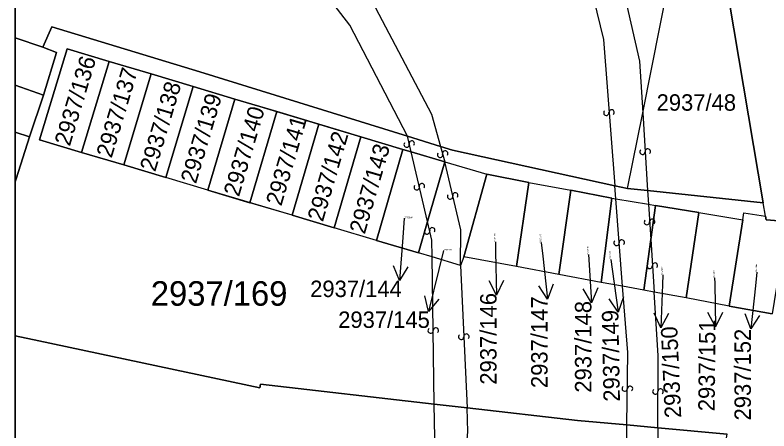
# Model space of a CAD drawing. Extents: x -596024 to -594475, y -1163820 to -1161957.
# Drawn here: x -596024.4 to -595972.1, y -1163190.6 to -1163161.8 of the extents above; entities that cross this region are included whole.
import ezdxf

# ---------------------------------------------------------------- set-up
doc = ezdxf.new("R2010")
doc.units = 0
for name, color, linetype in [('Level 1', 7, 'Continuous'), ('Level 13', 7, 'Continuous'), ('Level 3', 7, 'Continuous'), ('Level 4', 7, 'Continuous'), ('Level 57', 7, 'Continuous'), ('Level 60', 7, 'Continuous'), ('Vrstva 60', 7, 'Continuous'), ('Vrstva 63', 7, 'Continuous')]:
    doc.layers.add(name, color=color, linetype=linetype)

msp = doc.modelspace()

# ---------------------------------------------------------------- linework, layer by layer
at = {"layer": 'Level 1'}
for p, q in [((-596024.42, -1163163.373), (-596022.5, -1163164.02)), ((-596024.42, -1163166.662), (-596022.45, -1163167.35)), ((-596023.41, -1163170.25), (-596024.42, -1163169.907)), ((-596024.42, -1163173.127), (-596024.35, -1163173.15)), ((-596024.35, -1163173.15), (-596024.42, -1163173.362))]:
    msp.add_line(p, q, dxfattribs=at)
for points in [[(-595980.87, -1163168.57), (-595978.45, -1163156.45)], [(-595972.5, -1163174.81), (-595975.56, -1163156.7)], [(-596022.5, -1163164.02), (-596021.88, -1163162.61), (-596011.6, -1163165.73), (-595997.19, -1163170.2)], [(-596022.45, -1163167.35), (-596021.55, -1163164.4), (-596022.5, -1163164.02)], [(-596017.9, -1163165.01), (-596020.8, -1163164.14), (-596022.72, -1163170.46), (-596019.81, -1163171.33)], [(-596017.9, -1163165.01), (-596019.81, -1163171.33)], [(-596014.98, -1163165.88), (-596017.9, -1163165.01)], [(-596016.88, -1163172.19), (-596014.98, -1163165.88)], [(-596012.07, -1163166.75), (-596014.98, -1163165.88)], [(-596013.96, -1163173.06), (-596012.07, -1163166.75)], [(-596009.16, -1163167.62), (-596012.07, -1163166.75)], [(-596022.45, -1163167.35), (-596023.41, -1163170.25)], [(-596009.16, -1163167.62), (-596011.04, -1163173.94)], [(-596006.25, -1163168.49), (-596009.16, -1163167.62)], [(-596008.12, -1163174.81), (-596006.25, -1163168.49)], [(-596003.34, -1163169.36), (-596006.25, -1163168.49)], [(-595981.92, -1163173.82), (-595980.87, -1163168.57)], [(-596003.34, -1163169.36), (-596005.2, -1163175.68)], [(-596000.43, -1163170.23), (-596003.34, -1163169.36)], [(-596023.41, -1163170.25), (-596024.35, -1163173.15)], [(-596002.28, -1163176.54), (-596000.43, -1163170.23)], [(-595997.52, -1163171.11), (-596000.43, -1163170.23)], [(-595997.19, -1163170.2), (-595994.9, -1163170.91)], [(-595982.81, -1163173.63), (-595994.06, -1163171.17), (-595994.9, -1163170.91)], [(-596019.81, -1163171.33), (-596016.88, -1163172.19)], [(-595997.52, -1163171.11), (-595999.35, -1163177.42)], [(-595996.94, -1163171.28), (-595997.52, -1163171.11)], [(-595994.6, -1163171.97), (-595996.94, -1163171.28)], [(-596016.88, -1163172.19), (-596013.96, -1163173.06)], [(-595995.8, -1163176.12), (-595994.6, -1163171.97)], [(-595994.6, -1163171.97), (-595991.69, -1163172.84)], [(-595991.69, -1163172.84), (-595993.27, -1163178.56)], [(-595988.78, -1163173.4), (-595991.69, -1163172.84)], [(-596011.04, -1163173.94), (-596013.96, -1163173.06)], [(-595989.63, -1163179.24), (-595988.78, -1163173.4)], [(-595988.78, -1163173.4), (-595985.86, -1163173.95)], [(-596011.04, -1163173.94), (-596008.12, -1163174.81)], [(-595985.86, -1163173.95), (-595986.69, -1163179.79)], [(-595983.01, -1163174.5), (-595985.86, -1163173.95)], [(-595982.81, -1163173.63), (-595981.92, -1163173.82)], [(-595981.92, -1163173.82), (-595980.53, -1163173.97)], [(-595980.53, -1163173.97), (-595972.5, -1163174.81)], [(-595983.74, -1163180.33), (-595983.01, -1163174.5)], [(-595983.01, -1163174.5), (-595982.73, -1163174.55)], [(-595982.73, -1163174.55), (-595980.47, -1163174.92)], [(-596005.2, -1163175.68), (-596008.12, -1163174.81)], [(-595980.47, -1163174.92), (-595979.99, -1163175)], [(-595979.99, -1163175), (-595980.31, -1163177.35)], [(-595976.97, -1163175.49), (-595979.99, -1163175)], [(-595972.34, -1163175.74), (-595972.5, -1163174.81)], [(-595977.85, -1163181.41), (-595976.97, -1163175.49)], [(-595976.97, -1163175.49), (-595973.93, -1163176)], [(-595973.93, -1163176), (-595973.85, -1163175.51), (-595972.34, -1163175.74)], [(-596005.2, -1163175.68), (-596002.28, -1163176.54)], [(-595996.43, -1163178.29), (-595995.8, -1163176.12)], [(-595973.93, -1163176), (-595974.87, -1163181.97)], [(-595972.34, -1163175.74), (-595972.3, -1163176), (-595970.84, -1163176.11)], [(-595999.35, -1163177.42), (-596002.28, -1163176.54)], [(-595999.35, -1163177.42), (-595996.43, -1163178.29)], [(-595980.31, -1163177.35), (-595980.8, -1163180.87)], [(-595995.48, -1163178.57), (-595996.43, -1163178.29)], [(-595993.51, -1163179.16), (-595995.48, -1163178.57)], [(-595993.27, -1163178.56), (-595993.51, -1163179.16)], [(-595989.63, -1163179.24), (-595993.27, -1163178.56)], [(-595986.69, -1163179.79), (-595989.63, -1163179.24)], [(-595983.74, -1163180.33), (-595986.69, -1163179.79)], [(-595982.26, -1163180.6), (-595983.74, -1163180.33)], [(-595980.8, -1163180.87), (-595982.26, -1163180.6)], [(-595980.08, -1163181), (-595980.8, -1163180.87)], [(-595977.85, -1163181.41), (-595980.08, -1163181)], [(-595974.87, -1163181.97), (-595977.85, -1163181.41)], [(-595974.87, -1163181.97), (-595971.88, -1163182.51)], [(-596024.42, -1163184.047), (-596022.76, -1163184.39), (-596007.44, -1163187.64), (-596007.39, -1163187.4), (-595995.33, -1163188.77)], [(-595995.33, -1163188.77), (-595993.06, -1163189.03)], [(-595981.96, -1163190.21), (-595985.4, -1163189.9), (-595993.06, -1163189.03)], [(-595981.96, -1163190.21), (-595979.83, -1163190.41)], [(-595979.83, -1163190.41), (-595975, -1163190.85)]]:
    msp.add_lwpolyline(points, dxfattribs=at)
at = {"layer": 'Level 13'}
for centre, start, end in [((-595983.394, -1163168.574), 131.6175, 4.2075), ((-595983.026, -1163168.547), 311.832, 183.93), ((-595997.25, -1163170.78), 140.4061, 12.5041), ((-595996.891, -1163170.699), 320.1916, 192.7816), ((-595994.927, -1163171.489), 142.9608, 15.5508), ((-595994.572, -1163171.391), 323.1752, 195.2732), ((-595980.884, -1163171.281), 130.761, 3.351), ((-595980.516, -1163171.26), 310.9755, 183.0735), ((-595996.191, -1163173.659), 320.412, 193.002), ((-595996.55, -1163173.741), 140.6265, 12.7244), ((-595994.23, -1163174.38), 140.4646, 12.5626), ((-595993.871, -1163174.299), 320.2502, 192.8402), ((-595980.574, -1163176.151), 130.9254, 3.5154), ((-595980.206, -1163176.13), 311.1399, 183.2379), ((-595995.471, -1163176.719), 320.3489, 192.9389), ((-595995.83, -1163176.8), 140.5633, 12.6613), ((-595982.684, -1163177.593), 131.8149, 3.9129), ((-595982.316, -1163177.567), 311.6004, 184.1904), ((-595980.384, -1163179.191), 130.7639, 3.3539), ((-595980.016, -1163179.17), 310.9784, 183.0764), ((-595995.584, -1163183.671), 128.2153, 0.3133), ((-595995.216, -1163183.668), 308.0008, 180.5908), ((-595993.464, -1163184.108), 129.7687, 2.3587), ((-595993.096, -1163184.093), 309.9832, 182.0812), ((-595982.114, -1163187.696), 126.6866, 358.7846), ((-595981.746, -1163187.703), 306.4721, 179.0621), ((-595979.994, -1163187.897), 127.0297, 359.1276), ((-595979.626, -1163187.902), 306.8152, 179.4052)]:
    msp.add_arc(centre, 0.184, start, end, dxfattribs=at)
at = {"layer": 'Level 3'}
for points in [[(-596022.62, -1163147.46), (-596010.7, -1163150.2), (-596003.3, -1163156.24), (-595999.4, -1163161.3), (-595995.53, -1163168.66), (-595994.9, -1163170.91)], [(-595997.19, -1163170.2), (-596001.2, -1163162.5), (-596004.77, -1163157.82), (-596011.4, -1163152.2), (-596023.6, -1163149.47)], [(-595985.85, -1163154.18), (-595983.6, -1163163.5), (-595982.81, -1163173.63)], [(-595983.38, -1163154.94), (-595981.1, -1163165), (-595980.87, -1163168.57)], [(-595980.87, -1163168.57), (-595980.53, -1163173.97)], [(-595996.94, -1163171.28), (-595997.19, -1163170.2)], [(-595994.9, -1163170.91), (-595994.6, -1163171.97)], [(-595995.8, -1163176.12), (-595996.94, -1163171.28)], [(-595993.51, -1163179.16), (-595993.5, -1163176.7), (-595994.6, -1163171.97)], [(-595982.73, -1163174.55), (-595982.81, -1163173.63)], [(-595980.53, -1163173.97), (-595980.47, -1163174.92)], [(-595982.26, -1163180.6), (-595982.73, -1163174.55)], [(-595980.47, -1163174.92), (-595980.31, -1163177.35)], [(-595995.48, -1163178.57), (-595995.5, -1163177.4), (-595995.8, -1163176.12)], [(-595980.31, -1163177.35), (-595980.08, -1163181)], [(-595995.33, -1163188.77), (-595995.48, -1163178.57)], [(-595993.51, -1163179.16), (-595993.06, -1163189.03)], [(-595981.96, -1163190.21), (-595981.9, -1163185.2), (-595982.26, -1163180.6)], [(-595979.83, -1163190.41), (-595979.8, -1163185.4), (-595980.08, -1163181)], [(-595995.74, -1163201), (-595995.3, -1163191.1), (-595995.33, -1163188.77)], [(-595993.93, -1163201.27), (-595993, -1163190.7), (-595993.06, -1163189.03)], [(-595982.1, -1163201.3), (-595981.96, -1163190.21)], [(-595979.83, -1163190.41), (-595979.9, -1163201.1)]]:
    msp.add_lwpolyline(points, dxfattribs=at)
at = {"layer": 'Level 57'}
for p, q in [((-595997.41, -1163175.88), (-595997.512, -1163177.219)), ((-595997.512, -1163177.219), (-595997.74, -1163180.21)), ((-595991.09, -1163177.53), (-595991.075, -1163178.221)), ((-595987.91, -1163177.57), (-595987.804, -1163178.522)), ((-595994.68, -1163178.12), (-595995.011, -1163179.44)), ((-595991.075, -1163178.221), (-595991.01, -1163181.22)), ((-595987.804, -1163178.522), (-595987.47, -1163181.503)), ((-595984.64, -1163178.41), (-595984.618, -1163178.756)), ((-595984.618, -1163178.756), (-595984.43, -1163181.75)), ((-595983.09, -1163178.75), (-595982.992, -1163179.42)), ((-595995.011, -1163179.44), (-595995.74, -1163182.35)), ((-595982.992, -1163179.42), (-595982.56, -1163182.389)), ((-595972.94, -1163179.62), (-595973.042, -1163180.577)), ((-595979.47, -1163179.82), (-595979.496, -1163180.478)), ((-595975.88, -1163180.01), (-595975.873, -1163180.421)), ((-595979.496, -1163180.478), (-595979.614, -1163183.476)), ((-595975.873, -1163180.421), (-595975.82, -1163183.421)), ((-595973.042, -1163180.577), (-595973.36, -1163183.56))]:
    msp.add_line(p, q, dxfattribs=at)
for points in [[(-595997.165, -1163179.251), (-595997.74, -1163180.21), (-595998.163, -1163179.175)], [(-595990.532, -1163180.21), (-595991.01, -1163181.22), (-595991.532, -1163180.231)], [(-595987.085, -1163180.454), (-595987.47, -1163181.503), (-595988.079, -1163180.565)], [(-595983.993, -1163180.721), (-595984.43, -1163181.75), (-595984.992, -1163180.783)], [(-595995.012, -1163181.502), (-595995.74, -1163182.35), (-595995.982, -1163181.258)], [(-595982.209, -1163181.327), (-595982.56, -1163182.389), (-595983.199, -1163181.471)], [(-595975.338, -1163182.412), (-595975.82, -1163183.421), (-595976.338, -1163182.429)], [(-595979.075, -1163182.496), (-595979.614, -1163183.476), (-595980.074, -1163182.457)], [(-595972.757, -1163182.619), (-595973.36, -1163183.56), (-595973.751, -1163182.513)]]:
    msp.add_lwpolyline(points, dxfattribs=at)
at = {"layer": 'Level 60'}
for points in [[(-595975.56, -1163156.7), (-595972.5, -1163174.81), (-595980.53, -1163173.97), (-595981.92, -1163173.82), (-595980.87, -1163168.57), (-595978.45, -1163156.45)], [(-595934.8, -1163175.73), (-595935.01, -1163178.73), (-595935.64, -1163178.68), (-595964.77, -1163176.56), (-595967.76, -1163176.33), (-595970.84, -1163176.11), (-595972.3, -1163176), (-595972.34, -1163175.74), (-595972.5, -1163174.81), (-595975.56, -1163156.7), (-595967.15, -1163157.44), (-595937.14, -1163160.09), (-595934.14, -1163160.35), (-595934.28, -1163163.52), (-595934.41, -1163166.54), (-595934.54, -1163169.53), (-595934.67, -1163172.64)], [(-596017.9, -1163165.01), (-596019.81, -1163171.33), (-596022.72, -1163170.46), (-596020.8, -1163164.14)], [(-596017.9, -1163165.01), (-596014.98, -1163165.88), (-596016.88, -1163172.19), (-596019.81, -1163171.33)], [(-596012.07, -1163166.75), (-596013.96, -1163173.06), (-596016.88, -1163172.19), (-596014.98, -1163165.88)], [(-596009.16, -1163167.62), (-596011.04, -1163173.94), (-596013.96, -1163173.06), (-596012.07, -1163166.75)], [(-596006.25, -1163168.49), (-596008.12, -1163174.81), (-596011.04, -1163173.94), (-596009.16, -1163167.62)], [(-596003.34, -1163169.36), (-596005.2, -1163175.68), (-596008.12, -1163174.81), (-596006.25, -1163168.49)], [(-596000.43, -1163170.23), (-596002.28, -1163176.54), (-596005.2, -1163175.68), (-596003.34, -1163169.36)], [(-595997.52, -1163171.11), (-595999.35, -1163177.42), (-596002.28, -1163176.54), (-596000.43, -1163170.23)], [(-595999.35, -1163177.42), (-595997.52, -1163171.11), (-595996.94, -1163171.28), (-595994.6, -1163171.97), (-595995.8, -1163176.12), (-595996.43, -1163178.29)], [(-595991.69, -1163172.84), (-595993.27, -1163178.56), (-595993.51, -1163179.16), (-595995.48, -1163178.57), (-595996.43, -1163178.29), (-595995.8, -1163176.12), (-595994.6, -1163171.97)], [(-595988.78, -1163173.4), (-595989.63, -1163179.24), (-595993.27, -1163178.56), (-595991.69, -1163172.84)], [(-595985.86, -1163173.95), (-595986.69, -1163179.79), (-595989.63, -1163179.24), (-595988.78, -1163173.4)], [(-595983.01, -1163174.5), (-595983.74, -1163180.33), (-595986.69, -1163179.79), (-595985.86, -1163173.95)], [(-595983.74, -1163180.33), (-595983.01, -1163174.5), (-595982.73, -1163174.55), (-595980.47, -1163174.92), (-595979.99, -1163175), (-595980.31, -1163177.35), (-595980.8, -1163180.87), (-595982.26, -1163180.6)], [(-595976.97, -1163175.49), (-595977.85, -1163181.41), (-595980.08, -1163181), (-595980.8, -1163180.87), (-595980.31, -1163177.35), (-595979.99, -1163175)], [(-595973.93, -1163176), (-595974.87, -1163181.97), (-595977.85, -1163181.41), (-595976.97, -1163175.49)], [(-595972.34, -1163175.74), (-595972.3, -1163176), (-595970.84, -1163176.11), (-595971.88, -1163182.51), (-595974.87, -1163181.97), (-595973.93, -1163176), (-595973.85, -1163175.51)]]:
    msp.add_lwpolyline(points, close=True, dxfattribs=at)
at = {"layer": 'Vrstva 60'}
for points in [[(-596024.42, -1163151.144), (-596024.42, -1163163.373), (-596022.5, -1163164.02), (-596021.88, -1163162.61), (-596011.6, -1163165.73), (-595997.19, -1163170.2), (-595994.9, -1163170.91), (-595994.06, -1163171.17), (-595982.81, -1163173.63), (-595981.92, -1163173.82), (-595980.87, -1163168.57), (-595978.45, -1163156.45), (-595983.38, -1163154.94), (-595985.85, -1163154.18), (-595992.05, -1163153.51), (-596004.08, -1163149.95), (-596011.4, -1163147.5), (-596012.73, -1163146.91), (-596019.54, -1163143.8), (-596020.59, -1163143.33), (-596022.62, -1163147.46), (-596023.6, -1163149.47)], [(-596024.42, -1163163.373), (-596024.42, -1163166.662), (-596022.45, -1163167.35), (-596021.55, -1163164.4), (-596022.5, -1163164.02)], [(-596024.42, -1163166.662), (-596024.42, -1163169.907), (-596023.41, -1163170.25), (-596022.45, -1163167.35)], [(-596024.42, -1163169.907), (-596024.42, -1163173.127), (-596024.35, -1163173.15), (-596023.41, -1163170.25)], [(-596024.42, -1163173.127), (-596024.42, -1163173.362), (-596024.35, -1163173.15)], [(-596024.42, -1163184.047), (-596024.42, -1163197.407), (-596006.03, -1163199.69), (-595997.58, -1163200.74), (-595995.74, -1163201), (-595993.93, -1163201.27), (-595990, -1163201.83), (-595982.1, -1163202.97), (-595979.92, -1163203.28), (-595978.28, -1163203.51), (-595977.18, -1163203.67), (-595977.14, -1163203.41), (-595976.67, -1163200.65), (-595975, -1163190.85), (-595979.83, -1163190.41), (-595981.96, -1163190.21), (-595985.4, -1163189.9), (-595993.06, -1163189.03), (-595995.33, -1163188.77), (-596007.39, -1163187.4), (-596007.44, -1163187.64), (-596022.76, -1163184.39)]]:
    msp.add_lwpolyline(points, close=True, dxfattribs=at)
msp.add_lwpolyline([(-595971.88, -1163182.51), (-595974.87, -1163181.97), (-595977.85, -1163181.41), (-595980.08, -1163181), (-595980.8, -1163180.87), (-595982.26, -1163180.6), (-595983.74, -1163180.33), (-595986.69, -1163179.79), (-595989.63, -1163179.24), (-595993.27, -1163178.56), (-595993.51, -1163179.16), (-595995.48, -1163178.57), (-595996.43, -1163178.29), (-595999.35, -1163177.42), (-596002.28, -1163176.54), (-596005.2, -1163175.68), (-596011.04, -1163173.94), (-596013.96, -1163173.06), (-596016.88, -1163172.19), (-596019.81, -1163171.33), (-596022.72, -1163170.46), (-596020.8, -1163164.14), (-596017.9, -1163165.01), (-596014.98, -1163165.88), (-596000.43, -1163170.23), (-595997.52, -1163171.11), (-595996.94, -1163171.28), (-595994.6, -1163171.97), (-595991.69, -1163172.84), (-595988.78, -1163173.4), (-595985.86, -1163173.95), (-595983.01, -1163174.5), (-595982.73, -1163174.55), (-595980.47, -1163174.92), (-595979.99, -1163175), (-595976.97, -1163175.49), (-595973.93, -1163176), (-595973.85, -1163175.51), (-595972.34, -1163175.74), (-595972.5, -1163174.81), (-595980.53, -1163173.97), (-595981.92, -1163173.82), (-595982.81, -1163173.63), (-595994.06, -1163171.17), (-595994.9, -1163170.91), (-595997.19, -1163170.2), (-596011.6, -1163165.73), (-596021.88, -1163162.61), (-596022.5, -1163164.02), (-596021.55, -1163164.4), (-596022.45, -1163167.35), (-596023.41, -1163170.25), (-596024.35, -1163173.15), (-596024.42, -1163173.362), (-596024.42, -1163184.047), (-596022.76, -1163184.39), (-596007.44, -1163187.64), (-596007.39, -1163187.4), (-595995.33, -1163188.77), (-595993.06, -1163189.03), (-595985.4, -1163189.9), (-595981.96, -1163190.21), (-595979.83, -1163190.41), (-595975, -1163190.85)], dxfattribs=at)
at = {"layer": 'Vrstva 63'}
msp.add_lwpolyline([(-594475.47, -1163820.23), (-596024.42, -1163820.23), (-596024.42, -1161956.88), (-594475.47, -1161956.88)], close=True, dxfattribs=at)

# ---------------------------------------------------------------- texts
at = {"layer": 'Level 4'}
for s, height, rotation, p in [('2937/136', 1.14, 73.1844, (-596020.622, -1163170.938)), ('2937/137', 1.14, 73.2425, (-596017.722, -1163171.757)), ('2937/138', 1.14, 73.3258, (-596014.698, -1163172.712)), ('2937/139', 1.14, 73.434, (-596011.869, -1163173.542)), ('2937/140', 1.14, 73.5172, (-596008.885, -1163174.44)), ('2937/141', 1.14, 73.6007, (-596005.948, -1163175.089)), ('2937/142', 1.14, 73.6596, (-596003.065, -1163176.178)), ('2937/143', 1.14, 73.827, (-596000.158, -1163177.038)), ('2937/146', 0.1, 90, (-595991.09, -1163177.53)), ('2937/147', 0.1, 90, (-595987.91, -1163177.57)), ('2937/148', 0.1, 90, (-595984.64, -1163178.41)), ('2937/149', 0.1, 91.0454, (-595983.09, -1163178.75)), ('2937/150', 0.1, 92.5813, (-595979.47, -1163179.82)), ('2937/152', 0.1, 90, (-595972.94, -1163179.62)), ('2937/151', 0.1, 89.4571, (-595975.88, -1163180.01))]:
    msp.add_text(s, height=height, rotation=rotation, dxfattribs=at).set_placement(p)
for s, height, p in [('2937/48', 1.14, (-595979.903, -1163168.43)), ('2937/144', 0.1, (-595997.41, -1163175.88)), ('2937/145', 0.1, (-595994.68, -1163178.12)), ('2937/169', 1.7, (-596015.003, -1163181.95))]:
    msp.add_text(s, height=height, dxfattribs=at).set_placement(p)
at = {"layer": 'Level 57'}
for s, p in [('2937/144', (-596003.944, -1163181.35)), ('2937/145', (-596001.999, -1163183.49))]:
    msp.add_text(s, height=1.14, dxfattribs=at).set_placement(p)
for s, rotation, p in [('2937/146', 90, (-595991.01, -1163187.424)), ('2937/147', 90, (-595987.47, -1163187.66)), ('2937/148', 90, (-595984.43, -1163187.978)), ('2937/149', 91.0454, (-595982.447, -1163188.592)), ('2937/150', 92.5813, (-595978.191, -1163189.709)), ('2937/151', 89.4571, (-595975.875, -1163189.27)), ('2937/152', 90, (-595973.36, -1163189.906))]:
    msp.add_text(s, height=1.14, rotation=rotation, dxfattribs=at).set_placement(p)

doc.saveas('drawing.dxf')
